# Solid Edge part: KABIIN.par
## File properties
Author: ke06
Template: Normal.par
Last saved by: Andris
Revision: 13
Application: Solid Edge
Accuracy: 0,990
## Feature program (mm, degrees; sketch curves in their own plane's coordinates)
sketch for "unnamed Protrusion 1" plane through (0, 0, 0) normal (1, 0, 0) x-axis (0, 1, 0)
  line (37.5, 0) -> (29.0003, 14.951)
  line (29.0003, 14.951) -> (18.9495, 27.1656)
  line (-18.9495, 27.1656) -> (18.9495, 27.1656)
  line (-29.0003, 14.951) -> (-18.9495, 27.1656)
  line (-37.5, 0) -> (-29.0003, 14.951)
  line (-37.5, 0) -> (37.5, 0)
extrude "unnamed Protrusion 1" add finite 159.2754 symmetric
chamfer "Chamfer_5" setback 25
thinwall "Thinwall_3"  Thickness = 3 mm
sketch for "ExtrudedCutout_3" plane through (-67.1377, 0, 14.6656) normal (-0.707107, 0, 0.707107) x-axis (0, -1, 0)
  line (-18.9495, 13.0727) -> (-32.4633, -15.4923)
  bspline degree 3 poles (-32.4633, -15.4923) (-10.8211, -15.4923) (10.8211, -15.4923) (32.4633, -15.4923) knots 0 1 multiplicities 4 4
  line (18.9495, 13.0727) -> (32.4633, -15.4923)
  bspline degree 3 poles (-18.9495, 13.0727) (-6.3612, 14.3273) (6.2717, 14.3273) (18.9495, 13.0727) knots 0 1 multiplicities 4 4
extrude "ExtrudedCutout_3" cut finite 72.2923 along -normal
sketch for "ExtrudedCutout_4" plane through (79.6377, 0, 13.5828) normal (1, 0, 0) x-axis (0, 1, 0)
  line (7.4407, -13.5828) -> (7.4407, 5.1807)
  line (7.4407, 5.1807) -> (20.0969, 5.1807)
  line (20.0969, 5.1807) -> (20.0969, -13.5828)
  line (20.0969, -13.5828) -> (7.4407, -13.5828)
extrude "ExtrudedCutout_4" cut finite 28.6432 along -normal
cool vent "Vent_3"  RibThickness = 1 mm; RibOffset = 0.5 mm; RibDepth = 3 mm; SparThickness = 1 mm; SparOffset = 0.5 mm; SparDepth = 3 mm
fillet "Round_4" radius 2
fillet "Round_5" radius 1
fillet "Round_6" radius 1
sketch for "ExtrudedCutout_6" plane through (0, 0, 0) normal (0, -1, 0) x-axis (1, 0, 0)
  bspline degree 3 poles (-44.0021, 19.4879) (-32.7619, 22.1855) (-21.2892, 22.1855) (-9.584, 19.4879) knots 0 1 multiplicities 4 4
  line (-9.584, 4.4879) -> (-9.584, 19.4879)
  line (-44.0021, 4.4879) -> (-9.584, 4.4879)
  line (-44.0021, 19.4879) -> (-44.0021, 4.4879)
extrude "ExtrudedCutout_6" cut finite 236.8306 symmetric
sketch for "ExtrudedCutout_7" plane through (0, 0, 0) normal (0, -1, 0) x-axis (1, 0, 0)
  bspline degree 3 poles (44.0021, 19.4879) (32.7619, 22.1855) (21.2892, 22.1855) (9.584, 19.4879) knots 0 1 multiplicities 4 4
  line (9.584, 4.4879) -> (9.584, 19.4879)
  line (44.0021, 4.4879) -> (9.584, 4.4879)
  line (44.0021, 19.4879) -> (44.0021, 4.4879)
extrude "ExtrudedCutout_7" cut finite 305.1183 symmetric
sketch used by "unnamed Protrusion 2" plane through (-65.0164, 0, 12.5443) normal (0.707107, 0, -0.707107) x-axis (0, -1, 0)
extrude "unnamed Protrusion 2" add finite 2.9422 along -normal
sketch for "ExtrudedProtrusion_4" plane through (-9.584, 0, 0) normal (1, 0, 0) x-axis (0, 1, 0)
  line (-22.0143, 22.2523) -> (-34.1557, 4.4879)
  line (-32.6929, 4.4879) -> (-34.1557, 4.4879)
  line (-32.6929, 4.4879) -> (-20.5555, 22.3118)
  line (-20.5555, 22.3118) -> (-22.0143, 22.2523)
extrude "ExtrudedProtrusion_4" add finite 37.1471 along -normal
mirror "unnamed Mirror 1" of "ExtrudedProtrusion_4" about plane through (0, 0, 0) normal (0, -1, 0)
extrude "unnamed Protrusion 3" add finite 37.1471
sketch for "ExtrudedProtrusion_6" plane through (44.0021, 0, 0) normal (1, 0, 0) x-axis (0, 1, 0)
  line (-22.0143, 22.2523) -> (-34.1557, 4.4879)
  line (-34.1557, 4.4879) -> (-32.731, 4.4879)
  line (-32.731, 4.4879) -> (-20.5555, 22.3118)
  line (-20.5555, 22.3118) -> (-22.0143, 22.2523)
extrude "ExtrudedProtrusion_6" add finite 35.0644 along -normal
mirror "unnamed Mirror 2" of "ExtrudedProtrusion_6" about plane through (0, 0, 0) normal (0, -1, 0)
extrude "unnamed Protrusion 4" add finite 35.0644
sketch for "ExtrudedProtrusion_8" plane through (78.1377, 0, 12.5828) normal (1, 0, 0) x-axis (0, 1, 0)
  line (7.4407, 6.1807) -> (20.0969, 6.1807)
  line (20.0969, 6.1807) -> (20.0969, -12.5828)
  line (20.0969, -12.5828) -> (7.4407, -12.5828)
  line (7.4407, -12.5828) -> (7.4407, 6.1807)
extrude "ExtrudedProtrusion_8" add finite 1.1289 symmetric
sketch for "ExtrudedProtrusion_9" plane through (78.7021, 13.7688, 9.3818) normal (1, 0, 0) x-axis (0, 1, 0)
  circle centre (4.3416, -0.2078) radius 0.3518
extrude "ExtrudedProtrusion_9" add finite 2.3173 along +normal
sketch used by "ExtrudedProtrusion_10" plane through (11.7071, 0, 30.6415) normal (0, 0, 1) x-axis (1, 0, 0)
extrude "ExtrudedProtrusion_10" add finite 1.5528 along -normal
lofted protrusion "unnamed LoftedProtrusion 1"
lofted protrusion "unnamed LoftedProtrusion 2"
fillet "Round_7" radius 1
fillet "Round_8" radius 1
fillet "Round_9" radius 1
helix protrusion "HelixProtrusion_4"  Pitch = 0.5 mm
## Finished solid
Body 1: solid body, 154 faces, 447 edges, 280 vertices.
  Faces by surface: plane 118, cylinder 17, swept 10, blend 2, cone 2, sphere 2, torus 2, spline 1
  Edges by curve: line 388, circle 20, intersection 18, ellipse 16, spline 5
Bounding box of the edges (mm; curved faces can reach further): 160.657 x 75.000 x 30.860, from (-79.6377, -37.5, 0) to (81.0195, 37.5, 30.86).
Cylindrical faces by radius (mm): R0.3518 x1, R1 x15, R2 x1
Conical faces (half-angle, radius in mm at the cone's reference point): 16.8675 deg R2.1611 x2
Toroidal faces (ring radius, tube radius in mm): R0.2993 r1 x2
Spherical faces by radius (mm): R1 x2
Planar faces by outward normal: +x 13, +y 14, +z 24, -x 12, -y 15, -z 17, oblique 23
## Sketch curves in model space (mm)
circle centre (78.7021, 18.1104, 9.1739) radius 0.3518
line (78.1377, 7.4407, 18.7635) -> (78.1377, 20.0969, 18.7635)
line (78.1377, 20.0969, 18.7635) -> (78.1377, 20.0969, 0)
line (78.1377, 20.0969, 0) -> (78.1377, 7.4407, 0)
line (78.1377, 7.4407, 0) -> (78.1377, 7.4407, 18.7635)
circle centre (-51.2339, -15.1827, 27.1656) radius 2.1611
circle centre (-51.2339, 15.1827, 27.1656) radius 2.1611
circle centre (-51.2339, -15.1827, 30.86) radius 1.041
circle centre (-51.2339, 15.1827, 30.86) radius 1.041
line (44.0021, -34.1557, 4.4879) -> (44.0021, -32.731, 4.4879)
line (44.0021, -32.731, 4.4879) -> (44.0021, -20.5555, 22.3118)
line (44.0021, -20.5555, 22.3118) -> (44.0021, -22.0143, 22.2523)
line (44.0021, -22.0143, 22.2523) -> (44.0021, -34.1557, 4.4879)
line (-9.584, -22.0143, 22.2523) -> (-9.584, -34.1557, 4.4879)
line (-9.584, -20.5555, 22.3118) -> (-9.584, -22.0143, 22.2523)
line (-9.584, -32.6929, 4.4879) -> (-9.584, -20.5555, 22.3118)
line (-9.584, -32.6929, 4.4879) -> (-9.584, -34.1557, 4.4879)
line (55.3494, -12.4921, 30.6415) -> (58.3764, -14.2738, 30.6415)
line (58.3764, -14.2738, 30.6415) -> (73.3251, 11.1228, 30.6415)
line (73.3251, 11.1228, 30.6415) -> (70.2438, 12.8124, 30.6415)
line (70.2438, 12.8124, 30.6415) -> (55.3494, -12.4921, 30.6415)
line (-44.0021, 0, 4.4879) -> (-9.584, 0, 4.4879)
line (-9.584, 0, 4.4879) -> (-9.584, 0, 19.4879)
spline (-44.0021, 0, 19.4879) -> (-26.9674, 0, 21.5111) -> (-9.584, 0, 19.4879)
line (-44.0021, 0, 19.4879) -> (-44.0021, 0, 4.4879)
line (9.584, 0, 4.4879) -> (9.584, 0, 19.4879)
spline (44.0021, 0, 19.4879) -> (26.9674, 0, 21.5111) -> (9.584, 0, 19.4879)
line (44.0021, 0, 19.4879) -> (44.0021, 0, 4.4879)
line (44.0021, 0, 4.4879) -> (9.584, 0, 4.4879)
line (79.6377, -15.4868, 17.4657) -> (79.6377, -15.4868, 9.3757)
line (79.6377, -12.0999, 17.4657) -> (79.6377, -12.0999, 9.3757)
line (79.6377, -19.1929, 17.4657) -> (79.6377, -19.1929, 9.3757)
line (79.6377, -23.046, 14.6607) -> (79.6377, -7.9275, 14.6607)
line (79.6377, -23.046, 11.6009) -> (79.6377, -7.9275, 11.6009)
line (79.6377, -7.9275, 17.4657) -> (79.6377, -7.9275, 9.3757)
line (79.6377, -7.9275, 9.3757) -> (79.6377, -23.046, 9.3757)
line (79.6377, -23.046, 9.3757) -> (79.6377, -23.046, 17.4657)
line (79.6377, -23.046, 17.4657) -> (79.6377, -7.9275, 17.4657)
line (-75.9711, -32.4633, 1.5896) -> (-55.7726, -18.9495, 21.7881)
spline (-55.7726, 18.9495, 21.7881) -> (-55.1283, -0.033, 22.4324) -> (-55.7726, -18.9495, 21.7881)
line (-75.9711, 32.4633, 1.5896) -> (-55.7726, 18.9495, 21.7881)
line (-75.9711, 32.4633, 1.5896) -> (-75.9711, -32.4633, 1.5896)
circle centre (64.6515, 0, 27.1656) radius 0.2
line (64.3251, 0, 29.0887) -> (64.3251, 0, 27.1656)
line (0, -29.0003, 14.951) -> (0, -18.9495, 27.1656)
line (0, -18.9495, 27.1656) -> (0, 18.9495, 27.1656)
line (0, 29.0003, 14.951) -> (0, 18.9495, 27.1656)
line (0, 37.5, 0) -> (0, 29.0003, 14.951)
line (0, -37.5, 0) -> (0, 37.5, 0)
line (0, -37.5, 0) -> (0, -29.0003, 14.951)
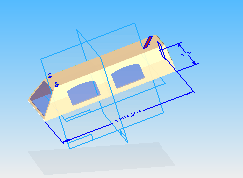
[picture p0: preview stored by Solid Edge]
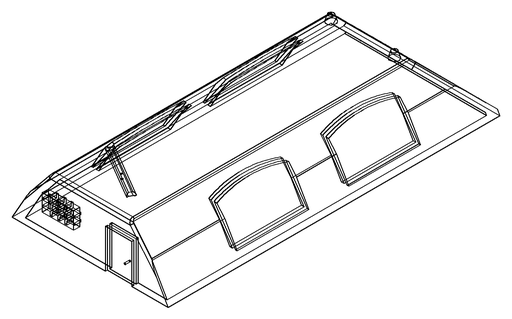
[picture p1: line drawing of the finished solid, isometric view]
